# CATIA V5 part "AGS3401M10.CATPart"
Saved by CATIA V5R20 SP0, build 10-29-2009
Part number: AGS3401M10
Definition: NONE
Nomenclature: AGS3401M10
Source: Unknown
Description: AGS3401M10
Bounding box of the stored display mesh (mm): x -20 to 35, y -12.5 to 12.5, z -10 to 10
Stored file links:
  C:\Users\Utente\Desktop\IO LAVORO\3D X SITO CF\X SITO\PLASTICA\AGS\AGS3401M10.CATPart
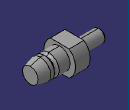
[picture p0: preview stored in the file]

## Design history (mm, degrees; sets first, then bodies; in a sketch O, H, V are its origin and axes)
Body1 "AGS3401M10" (main body)
  Solid1: solid without history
